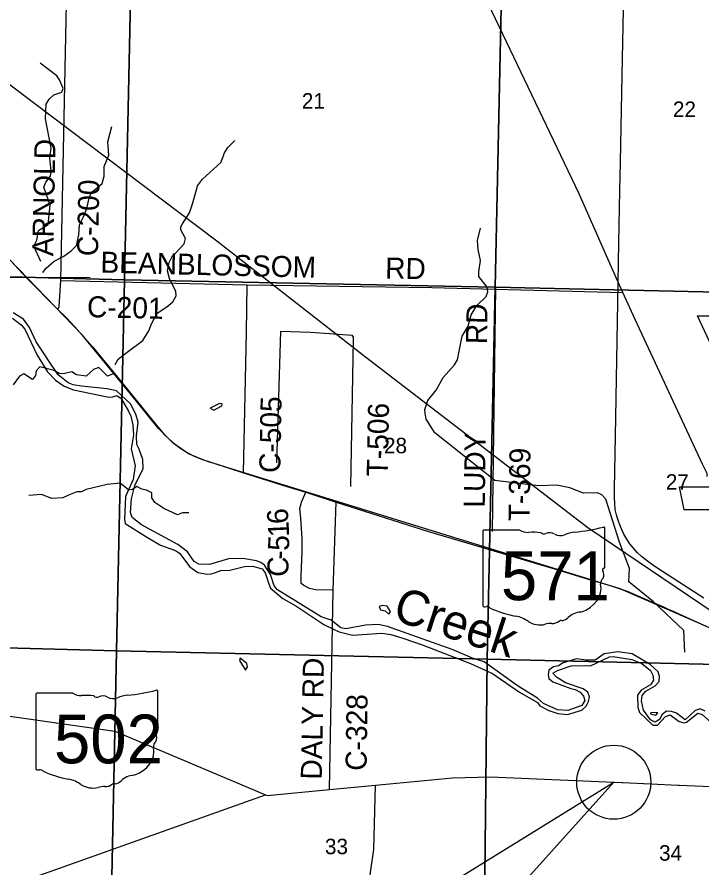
# Model space of a CAD drawing. Extents: x 0 to 68.9, y -26.1 to 22.
# Drawn here: x 2.979 to 4.831, y 17.359 to 19.658 of the extents above; entities that cross this region are included whole.
import ezdxf

# ---------------------------------------------------------------- set-up
doc = ezdxf.new("R2010")
doc.units = 0
for name, color, linetype in [('GM_X_Corporation', 7, 'Continuous'), ('GM_X_County_Road', 7, 'Continuous'), ('GM_X_County_Road_Text', 7, 'Continuous'), ('GM_X_Major_River', 7, 'Continuous'), ('GM_X_Major_River_Text', 7, 'Continuous'), ('GM_X_Minor_Lake', 7, 'Continuous'), ('GM_X_Minor_River', 7, 'Continuous'), ('GM_X_Rail_Line', 7, 'Continuous'), ('GM_X_Section_Text', 7, 'Continuous'), ('GM_X_State_Location', 7, 'Continuous'), ('GM_X_State_Route', 7, 'Continuous'), ('GM_X_State_Shield', 7, 'Continuous'), ('GM_X_Township_Road', 7, 'Continuous'), ('GM_X_Township_Road_Text', 7, 'Continuous'), ('SH_Text', 7, 'Continuous')]:
    doc.layers.add(name, color=color, linetype=linetype)

msp = doc.modelspace()

# ---------------------------------------------------------------- linework, layer by layer
at = {"layer": 'GM_X_Corporation'}
for points in [[(2.292, 19.9828), (3.2917, 19.9594), (3.2698, 18.9483), (2.2709, 18.9749)], [(3.2917, 19.9594), (4.2937, 19.9358), (4.2714, 18.9289), (3.2698, 18.9483)], [(4.2937, 19.9358), (5.2957, 19.9154), (5.2753, 18.9061), (4.2714, 18.9289)], [(2.2709, 18.9749), (3.2698, 18.9483), (3.2484, 17.9456), (2.2466, 17.9726)], [(3.2698, 18.9483), (4.2714, 18.9289), (4.25, 17.9235), (3.2484, 17.9456)], [(4.2714, 18.9289), (5.2753, 18.9061), (5.2626, 17.9001), (4.25, 17.9235)], [(2.2466, 17.9726), (3.2484, 17.9456), (3.2279, 16.9417), (3.215, 16.9416), (2.2241, 16.9661)], [(3.2484, 17.9456), (4.25, 17.9235), (4.2396, 16.9168), (4.218, 16.9165), (3.2279, 16.9417)], [(4.25, 17.9235), (5.2626, 17.9001), (5.2394, 16.9012), (5.2285, 16.9015), (4.2396, 16.9168)]]:
    msp.add_lwpolyline(points, close=True, dxfattribs=at)
for points in [[(5.0167, 18.4272), (4.8182, 18.8508), (5.0165, 18.8509)], [(5.0159, 18.3267), (4.7829, 18.3266), (4.7703, 18.3886), (5.0167, 18.3887)]]:
    msp.add_lwpolyline(points, dxfattribs=at)
at = {"layer": 'GM_X_County_Road'}
for points in [[(3.0894, 18.8685), (3.0937, 18.8759), (3.0977, 18.9468), (3.1188, 19.9596), (3.131, 20.4632)], [(3.0977, 18.9468), (3.6013, 18.9349), (4.1002, 18.9275), (4.6169, 18.9137)], [(3.5913, 18.427), (3.5994, 18.8073), (3.6013, 18.9349)], [(3.8337, 18.1098), (3.7866, 18.1105), (3.7696, 18.114), (3.7546, 18.1221), (3.7472, 18.1276), (3.7475, 18.1489), (3.7505, 18.2141), (3.75, 18.2491), (3.7464, 18.3047), (3.7441, 18.3306), (3.7484, 18.348), (3.7598, 18.3742)], [(3.8236, 17.5711), (3.8337, 18.1098), (3.8419, 18.3478)], [(3.7173, 15.8579), (3.731, 15.9214), (3.7945, 16.1638), (3.8415, 16.8765), (3.8451, 16.8958), (3.848, 16.9159), (3.8935, 17.0662), (3.9024, 17.0964), (3.9358, 17.3531), (3.9436, 17.4095), (3.9479, 17.5832)], [(1.927, 17.1327), (1.9962, 17.1249), (2.0915, 17.1109), (2.1668, 17.101), (2.275, 17.1011), (2.3585, 17.1122), (2.4483, 17.1304), (2.5619, 17.1695), (3.6511, 17.5566)]]:
    msp.add_lwpolyline(points, dxfattribs=at)
at = {"layer": 'GM_X_Major_River'}
for points in [[(3.3157, 18.2862), (3.2911, 18.3062), (3.2865, 18.3193), (3.2887, 18.3568), (3.298, 18.3927), (3.3205, 18.4389), (3.3196, 18.4633), (3.3097, 18.4905), (3.3029, 18.5036), (3.3023, 18.5261), (3.3068, 18.564), (3.3005, 18.5858), (3.2864, 18.6132), (3.2486, 18.6484), (3.2233, 18.654), (3.1536, 18.6607), (3.1313, 18.6644), (3.1174, 18.6697), (3.091, 18.6917), (3.0611, 18.7358), (3.0545, 18.7455), (3.0308, 18.7807), (3.0132, 18.8196), (2.9967, 18.8417), (2.9687, 18.8588)], [(2.9671, 18.8446), (2.9909, 18.8265), (3.0008, 18.8155), (3.0343, 18.7447), (3.0615, 18.6995), (3.0837, 18.6776), (3.1069, 18.6614), (3.1324, 18.6512), (3.2231, 18.6325), (3.2359, 18.6314), (3.2494, 18.636), (3.2605, 18.6281), (3.2809, 18.5934), (3.2874, 18.5799), (3.2924, 18.5566), (3.294, 18.5292), (3.2884, 18.492), (3.2986, 18.4454), (3.2938, 18.409), (3.2728, 18.3628), (3.2697, 18.3013), (3.2716, 18.2902), (3.3321, 18.2518), (3.3673, 18.2314), (3.4079, 18.2171), (3.4187, 18.2096), (3.4466, 18.1727), (3.4682, 18.1577), (3.4936, 18.1533), (3.5038, 18.1541), (3.5161, 18.1576), (3.5303, 18.1626), (3.5546, 18.1642), (3.5944, 18.1738), (3.616, 18.1744), (3.6424, 18.1673), (3.6505, 18.1568), (3.6596, 18.1273), (3.6642, 18.1154), (3.698, 18.0875), (3.7328, 18.0679), (3.8086, 18.0169), (3.8363, 18.0037), (3.8502, 17.9976), (3.8864, 17.9887), (3.9652, 17.9935), (3.9894, 17.9898), (4.0218, 17.9798), (4.0775, 17.9613), (4.2053, 17.912), (4.2642, 17.885), (4.3377, 17.834), (4.3861, 17.8065)], [(4.3861, 17.8179), (4.3362, 17.8483), (4.3221, 17.8582), (4.2423, 17.9165), (4.2103, 17.9265), (4.1555, 17.9492), (3.9805, 18.0115), (3.9552, 18.0167), (3.921, 18.0157), (3.8683, 18.0053), (3.8547, 18.0079), (3.8283, 18.0284), (3.8012, 18.0378), (3.6835, 18.1108), (3.6747, 18.1213), (3.6641, 18.1524), (3.6485, 18.1775), (3.638, 18.1843), (3.6268, 18.1895), (3.5897, 18.1954), (3.551, 18.1945), (3.4997, 18.1791), (3.4712, 18.1799), (3.4581, 18.187), (3.4398, 18.2134), (3.4141, 18.2334), (3.3157, 18.2862)], [(4.7854, 17.7598), (4.7614, 17.7773), (4.7485, 17.7821), (4.7349, 17.7827), (4.7229, 17.7742), (4.7155, 17.7606), (4.704, 17.7536), (4.6915, 17.7595), (4.6726, 17.7853), (4.6673, 17.8109), (4.6687, 17.8249), (4.6788, 17.8369), (4.7041, 17.8513), (4.7146, 17.8633), (4.7159, 17.877), (4.7123, 17.8892), (4.691, 17.9093), (4.6417, 17.9379), (4.603, 17.9435), (4.5661, 17.9376), (4.5419, 17.9209), (4.5175, 17.9209), (4.505, 17.9227), (4.4914, 17.9244), (4.4558, 17.9132), (4.4428, 17.9051), (4.4298, 17.903), (4.4171, 17.8941), (4.4146, 17.8808), (4.4167, 17.8713), (4.4272, 17.862), (4.4759, 17.8437), (4.4884, 17.8416), (4.5012, 17.8342), (4.5109, 17.8233), (4.5142, 17.8115), (4.5063, 17.7983), (4.4677, 17.7845), (4.44, 17.7869), (4.4023, 17.8039), (4.3861, 17.8179)], [(4.3861, 17.8065), (4.3923, 17.7972), (4.4164, 17.7846), (4.441, 17.7762), (4.4668, 17.7743), (4.5061, 17.7858), (4.5177, 17.7966), (4.5244, 17.8087), (4.5269, 17.8216), (4.5221, 17.8338), (4.5098, 17.8431), (4.4614, 17.8599), (4.4373, 17.8744), (4.428, 17.8852), (4.4399, 17.893), (4.4774, 17.9053), (4.5161, 17.9065), (4.529, 17.9052), (4.5811, 17.9294), (4.5907, 17.9304), (4.6415, 17.9227), (4.6683, 17.9116), (4.6915, 17.893), (4.6981, 17.8803), (4.6994, 17.8666), (4.6916, 17.8542), (4.6659, 17.8394), (4.6566, 17.8262), (4.6575, 17.7931), (4.6622, 17.7794), (4.6977, 17.745), (4.7107, 17.7447), (4.7324, 17.7687), (4.745, 17.7727), (4.7694, 17.7552), (4.7822, 17.7515), (4.7887, 17.7535)], [(4.839, 17.7825), (4.8254, 17.7892), (4.8124, 17.7845), (4.7854, 17.7598)], [(4.7887, 17.7535), (4.8191, 17.7771), (4.8316, 17.7735), (4.8563, 17.7514), (4.8738, 17.7295), (4.8878, 17.7239), (4.9218, 17.6903), (4.9473, 17.6697), (5.0057, 17.6147), (5.0318, 17.5946)]]:
    msp.add_lwpolyline(points, dxfattribs=at)
at = {"layer": 'GM_X_Minor_Lake'}
for points in [[(3.5334, 18.608), (3.5342, 18.6137), (3.527, 18.6138), (3.5018, 18.6012)], [(3.5018, 18.6012), (3.5116, 18.5962), (3.5334, 18.608)], [(3.9794, 18.0668), (3.9665, 18.0685), (3.9585, 18.0655), (3.9615, 18.0571), (3.974, 18.0543)], [(3.974, 18.0543), (3.9848, 18.0447), (3.9887, 18.0519), (3.9794, 18.0668)], [(3.583, 17.9258), (3.581, 17.9201), (3.5974, 17.8937)], [(3.5974, 17.8937), (3.6024, 17.9027), (3.6003, 17.9115), (3.583, 17.9258)], [(4.7116, 17.7785), (4.6923, 17.7795), (4.6915, 17.7761)], [(4.6915, 17.7761), (4.7062, 17.7725), (4.7116, 17.7785)]]:
    msp.add_lwpolyline(points, dxfattribs=at)
at = {"layer": 'GM_X_Minor_River'}
for points in [[(3.0577, 19.2123), (3.0698, 19.2289), (3.0716, 19.2422), (3.0685, 19.2789), (3.0716, 19.3043), (3.0564, 19.3835), (3.0583, 19.4231), (3.0665, 19.4367), (3.0789, 19.4479), (3.1002, 19.4555), (3.1038, 19.4653), (3.0944, 19.4887), (3.0867, 19.4992), (3.0419, 19.5336)], [(3.2095, 19.2086), (3.2147, 19.2285), (3.2151, 19.2543), (3.2274, 19.2849), (3.2248, 19.3214), (3.2353, 19.3631)], [(3.4672, 19.2024), (3.4809, 19.2205), (3.5299, 19.2658), (3.5379, 19.2833), (3.5393, 19.2893), (3.5494, 19.3055), (3.5681, 19.3247)], [(3.0434, 18.9979), (3.0249, 19.0397), (3.0327, 19.0555), (3.0372, 19.0813), (3.0632, 19.0981), (3.0688, 19.15), (3.0515, 19.1989), (3.0577, 19.2123)], [(3.0489, 18.9683), (3.0579, 18.9798), (3.08, 18.9986), (3.1062, 19.0124), (3.1259, 19.0267), (3.1403, 19.0408), (3.1464, 19.0695), (3.1486, 19.0969), (3.1594, 19.1186), (3.1683, 19.1408), (3.1756, 19.1733), (3.182, 19.185), (3.2095, 19.2086)], [(3.2451, 18.7195), (3.2529, 18.7337), (3.2699, 18.7477), (3.3199, 18.7848), (3.3353, 18.8103), (3.3427, 18.8299), (3.3582, 18.858), (3.3841, 18.8756), (3.4008, 18.8885), (3.4092, 18.905), (3.4091, 18.9168), (3.3917, 18.9518), (3.3866, 18.9725), (3.3906, 18.9952), (3.3997, 19.0132), (3.406, 19.0188), (3.4083, 19.021), (3.4313, 19.0459), (3.4344, 19.0602), (3.4224, 19.083), (3.4219, 19.0917), (3.4263, 19.1), (3.446, 19.1291), (3.4535, 19.154), (3.4664, 19.1982), (3.4672, 19.2024)], [(4.7847, 17.9422), (4.7819, 18.0008), (4.7, 18.0782), (4.6333, 18.1321), (4.6347, 18.1686), (4.6081, 18.2398), (4.5709, 18.356), (4.5601, 18.3672), (4.548, 18.3731), (4.5108, 18.3718), (4.4738, 18.3865), (4.4386, 18.3939), (4.3891, 18.3917), (4.2708, 18.4058), (4.1088, 18.5347), (4.0851, 18.5716), (4.0823, 18.588), (4.0821, 18.5983), (4.0901, 18.6221), (4.1119, 18.6499), (4.1311, 18.6849), (4.162, 18.719), (4.1695, 18.7322), (4.1748, 18.756), (4.1827, 18.7962), (4.1988, 18.8233), (4.2069, 18.8539), (4.2225, 18.8791), (4.2473, 18.9034), (4.2516, 18.9155), (4.25, 18.9285), (4.228, 18.957), (4.2279, 18.9703), (4.2318, 19.0003), (4.2254, 19.03), (4.2243, 19.0547), (4.2321, 19.0877)], [(3.2394, 18.6947), (3.2239, 18.688), (3.2004, 18.7116), (3.1866, 18.7057), (3.1662, 18.6878), (3.14, 18.6913), (3.1276, 18.6995), (3.1047, 18.6946), (3.0933, 18.6955), (3.0798, 18.7038), (3.0408, 18.7136), (3.0311, 18.7023), (3.0298, 18.6898), (3.0212, 18.6793), (2.9979, 18.6946), (2.986, 18.6883), (2.9693, 18.665)], [(3.4435, 18.3185), (3.4263, 18.3192), (3.413, 18.3137), (3.376, 18.3303), (3.3516, 18.3463), (3.3438, 18.3594), (3.3436, 18.3727), (3.3297, 18.3798), (3.3168, 18.3823), (3.3036, 18.3901), (3.2913, 18.3816), (3.2818, 18.3802), (3.2582, 18.3992), (3.2232, 18.3949), (3.1667, 18.3818), (3.1537, 18.3759), (3.1411, 18.3758), (3.1185, 18.3663), (3.1036, 18.3597), (3.0736, 18.3576), (3.0452, 18.3683), (3.0114, 18.3655)]]:
    msp.add_lwpolyline(points, dxfattribs=at)
at = {"layer": 'GM_X_Rail_Line'}
for points in [[(4.9304, 18.0029), (4.5219, 18.278), (3.9213, 18.739), (3.5195, 19.0528), (3.0238, 19.4269), (2.3664, 19.9252), (1.927, 20.2517)], [(4.96, 17.8329), (4.9023, 17.8299), (4.905, 17.9845), (4.6094, 18.1135), (3.5465, 18.441), (3.4843, 18.4615), (3.4425, 18.4786), (3.4016, 18.5067), (3.3614, 18.5468), (3.3023, 18.6209), (3.1558, 18.8), (2.8841, 19.0797), (2.8257, 19.1387), (2.6615, 19.27), (2.3538, 19.5236), (2.1141, 19.7092), (1.927, 19.8578)], [(4.8359, 18.0883), (4.711, 18.1686), (4.694, 18.1803), (4.6795, 18.1909), (4.6675, 18.2007), (4.6556, 18.2119), (4.6452, 18.2229), (4.6359, 18.2346), (4.6272, 18.248), (4.6194, 18.2611), (4.6101, 18.2816), (4.6039, 18.2984), (4.5998, 18.3131), (4.5965, 18.3281), (4.5948, 18.3436), (4.594, 18.3591), (4.5939, 18.3833), (4.5968, 18.526), (4.6033, 18.887), (4.6062, 19.0496), (4.6088, 19.1894), (4.6103, 19.2662), (4.6151, 19.5012), (4.6195, 19.7243)]]:
    msp.add_lwpolyline(points, dxfattribs=at)
at = {"layer": 'GM_X_State_Route'}
for p, q in [((4.6169, 18.9137), (4.5998, 18.9522)), ((4.6504, 18.8416), (4.6169, 18.9137))]:
    msp.add_line(p, q, dxfattribs=at)
for points in [[(4.5998, 18.9522), (4.4985, 19.1804), (4.1746, 19.8594), (4.1406, 19.9306), (3.9247, 20.4486), (3.8136, 20.7161), (3.7609, 20.9)], [(1.927, 19.7915), (2.0947, 19.7182), (2.1112, 19.7099), (2.1156, 19.7076), (2.1315, 19.6973), (2.1637, 19.6737), (2.2221, 19.6281), (2.2754, 19.5865), (2.357, 19.5226), (2.5689, 19.3502), (2.7263, 19.221), (2.8172, 19.1457), (2.8441, 19.1214), (2.8944, 19.0691), (2.9626, 18.9999), (3.0043, 18.9545), (3.0894, 18.8685), (3.1128, 18.8456), (3.1358, 18.8218), (3.1838, 18.7675), (3.2512, 18.6855), (3.3589, 18.5525), (3.3608, 18.5502)], [(4.8443, 18.4167), (4.8444, 18.4247), (4.8325, 18.4501), (4.6504, 18.8416)], [(3.3608, 18.5502), (3.3772, 18.5306), (3.3897, 18.5188), (3.4049, 18.5055), (3.4222, 18.4925), (3.4389, 18.4817), (3.456, 18.4725), (3.4781, 18.4636), (3.4991, 18.4567)], [(3.4991, 18.4567), (3.5087, 18.4536), (3.5913, 18.427), (3.7091, 18.3899), (3.7598, 18.3742), (3.8419, 18.3478), (4.0918, 18.2686), (4.2347, 18.2263), (4.4413, 18.1646), (4.5235, 18.14), (4.5581, 18.1294), (4.5877, 18.1204)], [(4.5877, 18.1204), (4.6066, 18.1145), (4.6284, 18.107), (4.6636, 18.0919), (4.6921, 18.0791), (4.7271, 18.0644), (4.7379, 18.0596)], [(4.7379, 18.0596), (4.7468, 18.0555), (4.8394, 18.0134)], [(2.8268, 17.7887), (3.2441, 17.7287), (3.6511, 17.5566)], [(3.6511, 17.5566), (3.6554, 17.5547), (3.8236, 17.5711), (3.9479, 17.5832), (4.1563, 17.6024), (4.2589, 17.6052), (4.6145, 17.5899), (4.6166, 17.5899)], [(4.6166, 17.5899), (4.7661, 17.5834), (4.7691, 17.5833)], [(4.7691, 17.5833), (4.8984, 17.5777), (4.9218, 17.573), (4.9468, 17.567), (4.964, 17.556), (4.9796, 17.5419), (5.0234, 17.4872), (5.0702, 17.4287), (5.0762, 17.4335), (5.082, 17.4382), (5.085, 17.4406)]]:
    msp.add_lwpolyline(points, dxfattribs=at)
at = {"layer": 'GM_X_State_Shield'}
for p, q in [((4.2387, 18.2688), (4.2387, 18.0687)), ((4.3385, 18.2722), (4.2419, 18.2722)), ((4.5683, 18.1725), (4.5683, 18.2772)), ((4.5682, 18.1725), (4.5683, 18.1725)), ((3.0304, 17.8279), (3.0304, 17.6278)), ((3.1301, 17.8314), (3.0336, 17.8314)), ((3.36, 17.7317), (3.36, 17.8363)), ((3.3599, 17.7317), (3.36, 17.7317))]:
    msp.add_line(p, q, dxfattribs=at)
for centre, major_axis, start_param, end_param in [((4.4509, 18.545), (0.3495, 0), 4.814394, 5.042369), ((4.5646, 18.2776), (0.00367, 0), 6.141152, 7.989035), ((4.2425, 18.2692), (0.00382, 0), 1.712693, 3.28349), ((4.3614, 18.2954), (0.037, 0), 4.042523, 4.731795), ((4.3737, 18.1599), (0.133, 0), 1.404758, 1.657858), ((4.4039, 18.2702), (0.0107, 0), 3.836095, 5.185415), ((4.4196, 18.2471), (0.0222, 0), 0.950623, 2.079405), ((4.4483, 18.2788), (0.0267, 0), 4.081561, 5.145723), ((4.4955, 18.2111), (0.0703, 0), 1.699011, 2.107814), ((4.5674, 18.1648), (0.00568, 0), 1.883978, 3.671073), ((4.5644, 18.1721), (0.00393, 0), 5.05454, 6.418171), ((4.5814, 18.1287), (0.0248, 0), 2.387724, 3.262537), ((4.5313, 18.1516), (0.0341, 0), 5.934695, 6.695948), ((4.4705, 18.1154), (0.0874, 0), 5.101752, 6.440018), ((4.2425, 18.0682), (0.00385, 0), 3.00124, 4.508301), ((4.2431, 18.0887), (0.0294, 0), 4.665946, 4.897461), ((4.2491, 18.0571), (0.0106, 0), 0.519207, 1.627899), ((4.3829, 18.2369), (0.2524, 0), 4.195997, 4.488961), ((4.5073, 18.0125), (0.0479, 0), 1.647645, 2.488434), ((4.3077, 17.9787), (0.079, 0), 0.823519, 1.323587), ((4.4499, 18.0217), (0.00752, 0), 1.147584, 2.315152), ((4.4467, 18.0493), (0.0282, 0), 4.937069, 5.64225), ((4.3931, 18.0561), (0.0501, 0), 4.026481, 4.996735), ((4.422, 17.9869), (0.0412, 0), 1.495662, 1.94098), ((4.4257, 18.0411), (0.0267, 0), 4.691044, 5.507374), ((3.0341, 17.8284), (0.00382, 0), 1.712693, 3.28349), ((3.1531, 17.8546), (0.037, 0), 4.042523, 4.731795), ((3.1654, 17.719), (0.133, 0), 1.404758, 1.657858), ((3.1956, 17.8294), (0.0107, 0), 3.836095, 5.185415), ((3.2113, 17.8063), (0.0222, 0), 0.950623, 2.079405), ((3.2399, 17.838), (0.0267, 0), 4.081561, 5.145723), ((3.2871, 17.7703), (0.0703, 0), 1.699011, 2.107814), ((3.2425, 18.1042), (0.3495, 0), 4.814394, 5.042369), ((3.3563, 17.8368), (0.00367, 0), 6.141152, 7.989035), ((3.3591, 17.724), (0.00568, 0), 1.883978, 3.671073), ((3.356, 17.7313), (0.00393, 0), 5.05454, 6.418171), ((3.323, 17.7107), (0.0341, 0), 5.934695, 6.695948), ((3.2621, 17.6745), (0.0874, 0), 5.101752, 6.440018), ((3.3731, 17.6878), (0.0248, 0), 2.387724, 3.262537), ((3.0342, 17.6274), (0.00385, 0), 3.00124, 4.508301), ((3.0348, 17.6479), (0.0294, 0), 4.665946, 4.897461), ((3.0408, 17.6163), (0.0106, 0), 0.519207, 1.627899), ((3.1746, 17.7961), (0.2524, 0), 4.195997, 4.488961), ((3.0994, 17.5379), (0.079, 0), 0.823519, 1.323587), ((3.2383, 17.6084), (0.0282, 0), 4.937069, 5.64225), ((3.299, 17.5716), (0.0479, 0), 1.647645, 2.488434), ((3.1848, 17.6153), (0.0501, 0), 4.026481, 4.996735), ((3.2137, 17.5461), (0.0412, 0), 1.495662, 1.94098), ((3.2174, 17.6003), (0.0267, 0), 4.691044, 5.507374), ((3.2415, 17.5809), (0.00752, 0), 1.147584, 2.315152)]:
    msp.add_ellipse(centre, major_axis=major_axis, ratio=0.8, start_param=start_param, end_param=end_param, dxfattribs=at)
at = {"layer": 'GM_X_Township_Road'}
for p, q in [((4.2648, 18.2686), (4.2732, 18.9275)), ((3.7724, 18.8073), (3.8857, 18.7992))]:
    msp.add_line(p, q, dxfattribs=at)
for points in [[(2.1, 18.9765), (2.9158, 18.9557), (3.1773, 18.9545)], [(3.6817, 18.4536), (3.6924, 18.8093), (3.7724, 18.8073)], [(3.8821, 18.3899), (3.8889, 18.7862), (3.8886, 18.7931), (3.8857, 18.7992)]]:
    msp.add_lwpolyline(points, dxfattribs=at)
at = {"layer": 'SH_Text'}
for p, q in [((3.4804, 16.9057), (4.5923, 17.5909)), ((4.5923, 17.5909), (3.4804, 16.3557))]:
    msp.add_line(p, q, dxfattribs=at)
msp.add_circle((4.5923, 17.5909), 0.1, dxfattribs=at)

# ---------------------------------------------------------------- texts
at = {"layer": 'GM_X_County_Road_Text'}
for s, height, rotation, p in [('ARNOLD', 0.05682, 88.8443, (3.0772, 19.0118)), ('C-200', 0.05682, 88.8981, (3.1983, 19.0119)), ('BEANBLOSSOM', 0.056818, 358.6183, (3.2044, 18.9679)), ('RD', 0.05682, 359.0128, (3.9741, 18.952)), ('C-201', 0.05682, 358.6227, (3.1681, 18.8477)), ('C-505', 0.05682, 88.8984, (3.6908, 18.4261)), ('6', 0.0568, 93.9716, (3.7136, 18.2906)), ('1', 0.0568, 92.5688, (3.7152, 18.2544)), ('5', 0.0568, 89.0163, (3.7147, 18.2159)), ('-', 0.0568, 87.6183, (3.7136, 18.1912)), ('C', 0.0568, 88.1707, (3.7122, 18.1451)), ('DALY RD', 0.05682, 88.9103, (3.803, 17.5976)), ('C-328', 0.05682, 89.1736, (3.9241, 17.6216))]:
    msp.add_text(s, height=height, rotation=rotation, dxfattribs=at).set_placement(p)
at = {"layer": 'GM_X_Major_River_Text'}
msp.add_text('Creek', height=0.09469, rotation=342.0322, dxfattribs=at).set_placement((3.9909, 18.0307))
at = {"layer": 'GM_X_Section_Text'}
for s, p in [('21', (3.7492, 19.4109)), ('22', (4.7522, 19.3884)), ('28', (3.9713, 18.4797)), ('27', (4.733, 18.3814)), ('33', (3.8117, 17.3964)), ('34', (4.7147, 17.3789))]:
    msp.add_text(s, height=0.04186, rotation=0, dxfattribs=at).set_placement(p)
at = {"layer": 'GM_X_State_Location'}
for s, p in [('571', (4.3329, 18.1416)), ('502', (3.1246, 17.7008))]:
    msp.add_text(s, height=0.000189, rotation=0, dxfattribs=at).set_placement(p)
for s, p in [('s', (4.3998, 18.1554)), ('r', (4.3998, 18.1554)), ('s', (3.1915, 17.7146)), ('r', (3.1914, 17.7146))]:
    msp.add_text(s, height=0.000189, dxfattribs=at).set_placement(p)
at = {"layer": 'GM_X_State_Shield'}
for s, p in [('571', (4.2873, 18.0828)), ('502', (3.0794, 17.6419))]:
    msp.add_text(s, height=0.13184, dxfattribs=at).set_placement(p)
at = {"layer": 'GM_X_Township_Road_Text'}
for s, rotation, p in [('RD', 89.0123, (4.2494, 18.7742)), ('T-506', 88.8768, (3.9812, 18.4169)), ('LUDY', 89.2559, (4.2436, 18.3325)), ('T-369', 89.1574, (4.3645, 18.2957))]:
    msp.add_text(s, height=0.05682, rotation=rotation, dxfattribs=at).set_placement(p)

doc.saveas('drawing.dxf')
